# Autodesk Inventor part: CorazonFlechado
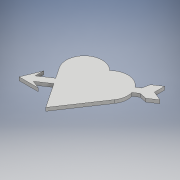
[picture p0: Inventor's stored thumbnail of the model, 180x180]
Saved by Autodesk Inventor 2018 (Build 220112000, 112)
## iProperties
Created: 2020-10
Part Number: CorazonFlechado
Material: Genérico
Document SubType Name: Modeling
Designer: ULISES
Density: 1 g/cm^3
Appearance: Valor por defecto
Author: ULISES
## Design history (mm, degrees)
sketch "Boceto1" dims "d1" = 35, "d2" = 35
  geometry: L1 (12.5, -50)-(39.528, -9.757); L2 (12.5, -50)-(-14.528, -9.757); L3 (-14.528, -9.757)-(39.528, -9.757); 3 further points
  constraints: 6 end point, 1 coincident, 1 horizontal alignment, 8 other
  dimensions: "d3" = 25 distance of point (0, 0) point (25, 0); "d4" = 50 vertical distance of L1.start point (25, 0); "d5" = 12.5 horizontal distance of point (25, 0) L1.start (= 0.5 x d3)
extrude "Extrusión1" new body sketch "Boceto1" distance "d6" = 3.2; taper "d7" = 0 deg
sketch "Boceto2"
  geometry: L1 (42.918, 13.313)-(-19.343, -28.503); L2 (-19.343, -28.503)-(-19.343, -20.07); L3 (-19.343, -20.07)-(-26.332, -37.172); L4 (-26.332, -37.172)-(-7.858, -37.172); L5 (-7.858, -37.172)-(-15.664, -33.982); L6 (-15.664, -33.982)-(46.598, 7.834); L7 (46.598, 7.834)-(53.466, 6.484); L8 (52.569, 15.819)-(52.569, 25.757); L9 (52.569, 25.757)-(44.267, 20.181); L10 (44.267, 20.181)-(42.918, 13.313); L11 (-14.528, -9.757)-(12.5, -50) reference; L12 (-19.343, -28.503)-(-15.664, -33.982); L13 (52.569, 15.819)-(61.768, 12.06); L14 (61.768, 12.06)-(53.466, 6.484)
  constraints: 27 end point, 5 perpendicular, 3 parallel, 1 vertical
  dimensions: "d33" = 6.6 distance between parallel lines of L6 L1; "d34" = 75 distance of L1.start L1.end; "d35" = 75 distance of L5.end L6.end; "d36" = 3.3 distance from line of L6 L3.end (= 0.5 x d33); "d37" = 7 distance from line of L6 L4.end; "d38" = 7 distance from line of L1 L2.end; "d39" = 10.63502 distance from line of L12 L3.end (derived); "d40" = 29 distance from line of L6 L11.end; "d41" = 3.3 distance from line of L8.start L6 (= 0.5 x d33); "d42" = 135 deg angle of L1 L10; "d43" = 7 distance of L9.end L1.start; "d44" = 7 distance of L6.end L7.end; "d45" = 10 distance of L8.end L9.end; "d47" = 10 distance of L13.end L7.end; "d48" = 3.3 distance from line of L1 L8.start (derived)
extrude "Extrusión2" join sketch "Boceto2" distance "d49" = 3.2; taper "d50" = 0 deg
node "Sólido1"
